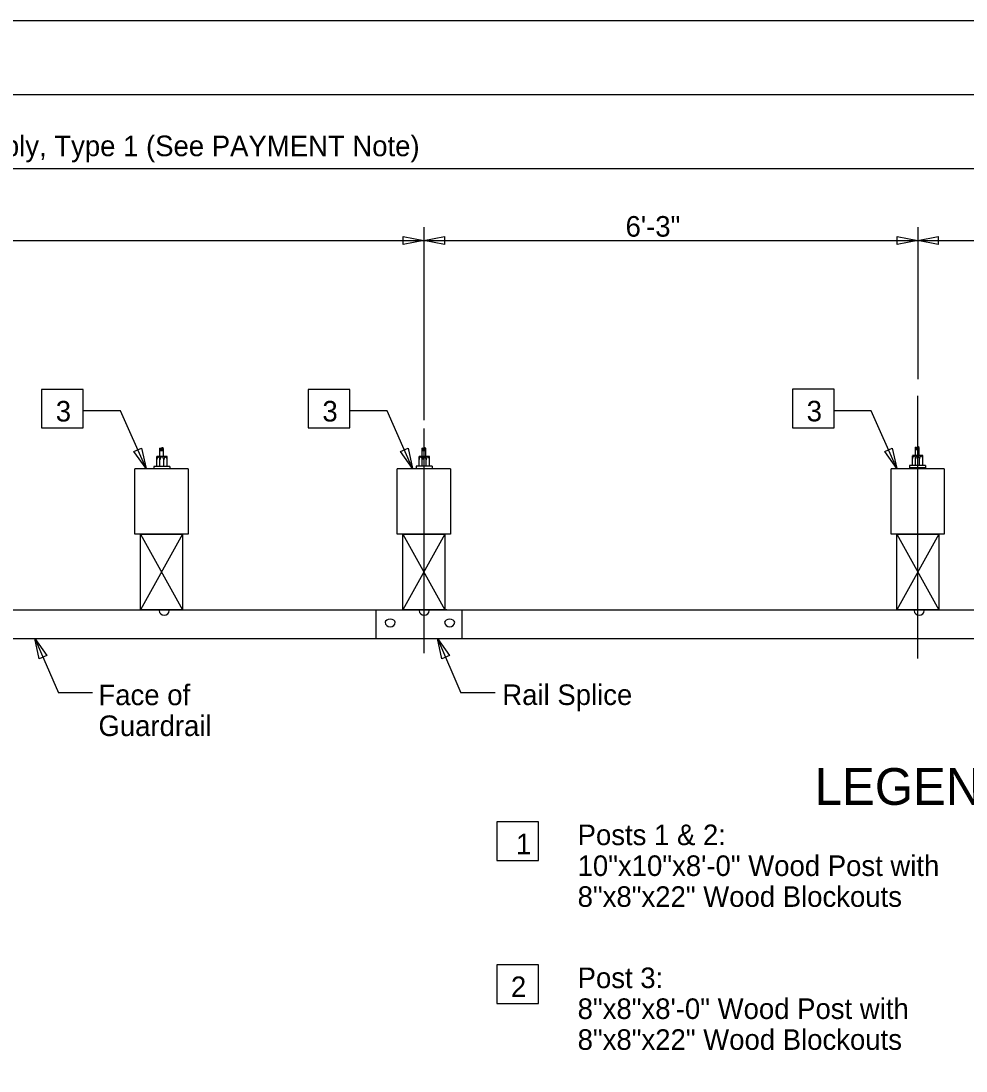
# Model space of a CAD drawing. Extents: x 0 to 34, y 0 to 22.
# Drawn here: x 12.13 to 18.56, y 14.86 to 22 of the extents above; entities that cross this region are included whole.
import ezdxf

# ---------------------------------------------------------------- set-up
doc = ezdxf.new("R2010")
doc.units = 0
for name, color, linetype in [('SH_Border', 7, 'Continuous'), ('SH_Cut_Line', 7, 'Continuous'), ('ST_Details', 7, 'Continuous'), ('ST_Text', 7, 'Continuous')]:
    doc.layers.add(name, color=color, linetype=linetype)

msp = doc.modelspace()

# ---------------------------------------------------------------- linework, layer by layer
at = {"layer": 'SH_Border'}
msp.add_lwpolyline([(2, 21.5), (33.5, 21.5), (33.5, 0.5), (2, 0.5)], close=True, dxfattribs=at)
at = {"layer": 'SH_Cut_Line'}
msp.add_lwpolyline([(0, 0), (34, 0), (34, 22), (0, 22)], close=True, dxfattribs=at)
at = {"layer": 'ST_Details'}
for p, q in [((18.2297, 19.4492), (18.2297, 17.664)), ((14.8702, 19.2267), (14.8702, 17.6984)), ((13.0734, 19.0942), (13.0811, 19.0957)), ((13.0734, 19.0434), (13.0734, 19.0942)), ((13.0991, 19.0899), (13.0734, 19.0899)), ((13.0991, 19.0832), (13.0734, 19.0832)), ((13.0991, 19.0752), (13.0734, 19.0752)), ((13.0922, 19.0957), (13.0838, 19.0957)), ((13.0991, 19.0923), (13.0922, 19.0957)), ((13.0991, 19.0415), (13.0991, 19.0923)), ((14.8591, 19.0951), (14.8668, 19.0965)), ((14.8591, 19.0442), (14.8591, 19.0951)), ((14.8847, 19.0908), (14.8591, 19.0908)), ((14.8847, 19.0841), (14.8591, 19.0841)), ((14.8847, 19.0761), (14.8591, 19.0761)), ((14.8779, 19.0965), (14.8697, 19.0965)), ((14.8847, 19.0932), (14.8779, 19.0965)), ((14.8847, 19.0423), (14.8847, 19.0932)), ((18.2171, 19.1007), (18.2247, 19.1021)), ((18.2171, 19.0497), (18.2171, 19.1007)), ((18.2425, 19.0964), (18.2171, 19.0964)), ((18.2425, 19.0896), (18.2171, 19.0896)), ((18.2425, 19.0816), (18.2171, 19.0816)), ((18.2357, 19.1021), (18.2274, 19.1021)), ((18.2425, 19.0988), (18.2357, 19.1021)), ((18.2425, 19.048), (18.2425, 19.0988)), ((13.124, 19.0369), (13.053, 19.0369)), ((13.053, 18.9713), (13.053, 19.0362)), ((13.0734, 18.9702), (13.0734, 19.0152)), ((13.0996, 18.9702), (13.0996, 19.0152)), ((13.124, 18.9694), (13.124, 19.0369)), ((14.9097, 19.0378), (14.8387, 19.0378)), ((14.8387, 18.9722), (14.8387, 19.0371)), ((14.8591, 18.971), (14.8591, 19.0162)), ((14.8852, 18.971), (14.8852, 19.0162)), ((14.9097, 18.9703), (14.9097, 19.0378)), ((18.2677, 19.0434), (18.1965, 19.0434)), ((18.1965, 18.9777), (18.1965, 19.0426)), ((18.2171, 18.9767), (18.2171, 19.0217)), ((18.2431, 18.9767), (18.2431, 19.0217)), ((18.2677, 18.9759), (18.2677, 19.0434)), ((12.9037, 18.5091), (12.9037, 18.9533)), ((13.2656, 18.9533), (12.9037, 18.9533)), ((13.142, 18.9533), (13.0311, 18.9533)), ((13.1417, 18.9702), (13.0334, 18.9702)), ((13.0334, 18.9702), (13.0334, 18.9533)), ((13.1417, 18.9702), (13.1417, 18.9533)), ((13.2656, 18.9533), (13.2656, 18.5091)), ((14.6894, 18.5091), (14.6894, 18.9533)), ((15.0512, 18.9533), (14.6894, 18.9533)), ((14.9276, 18.9543), (14.8169, 18.9543)), ((14.9271, 18.971), (14.8191, 18.971)), ((14.8191, 18.971), (14.8191, 18.9543)), ((14.9271, 18.971), (14.9271, 18.9543)), ((15.0512, 18.9533), (15.0512, 18.5091)), ((18.0511, 18.5091), (18.0511, 18.9533)), ((18.4129, 18.9533), (18.0511, 18.9533)), ((18.2855, 18.9598), (18.1747, 18.9598)), ((18.2851, 18.9767), (18.1767, 18.9767)), ((18.1767, 18.9767), (18.1767, 18.9598)), ((18.2851, 18.9767), (18.2851, 18.9598)), ((18.4129, 18.9533), (18.4129, 18.5091)), ((13.2656, 18.5091), (12.9037, 18.5091)), ((12.9418, 17.9934), (12.9418, 18.5091)), ((12.9418, 18.5091), (13.2275, 18.5091)), ((12.9418, 18.5091), (13.2275, 17.9934)), ((13.2275, 18.5091), (12.9418, 17.9934)), ((13.2275, 18.5091), (13.2275, 17.9934)), ((15.0512, 18.5091), (14.6894, 18.5091)), ((14.7275, 17.9934), (14.7275, 18.5091)), ((14.7275, 18.5091), (15.0131, 18.5091)), ((14.7275, 18.5091), (15.0131, 17.9934)), ((15.0131, 18.5091), (14.7275, 17.9934)), ((15.0131, 18.5091), (15.0131, 17.9934)), ((18.4129, 18.5091), (18.0511, 18.5091)), ((18.0892, 17.9934), (18.0892, 18.5091)), ((18.0892, 18.5091), (18.3749, 18.5091)), ((18.0892, 18.5091), (18.3749, 17.9934)), ((18.3749, 18.5091), (18.0892, 17.9934)), ((18.3749, 18.5091), (18.3749, 17.9934)), ((4.5018, 17.9934), (21.2687, 17.9934)), ((13.2275, 17.9934), (12.9418, 17.9934)), ((14.5458, 17.7999), (14.5458, 17.9934)), ((15.0131, 17.9934), (14.7275, 17.9934)), ((15.0278, 17.9934), (14.7422, 17.9934)), ((15.1314, 17.7999), (15.1314, 17.9934)), ((18.3749, 17.9934), (18.0892, 17.9934)), ((5.4066, 17.7999), (21.2687, 17.7999))]:
    msp.add_line(p, q, dxfattribs=at)
for centre, major_axis, ratio, start_param, end_param in [((13.0632, 19.0192), (0, -0.0142), 0.738563, 1.441228, 4.934001), ((13.0873, 19.0184), (0, -0.0169), 0.738563, 1.385306, 4.820506), ((13.1116, 19.0168), (0, -0.0162), 0.738563, 1.407193, 4.875853), ((14.8488, 19.0201), (0, -0.0142), 0.738563, 1.441228, 4.934001), ((14.873, 19.0193), (0, -0.0169), 0.738563, 1.385306, 4.820506), ((14.8972, 19.0177), (0, -0.0162), 0.738563, 1.407193, 4.875853), ((18.2067, 19.0257), (0, -0.0142), 0.738563, 1.441228, 4.934001), ((18.2309, 19.0248), (0, -0.0169), 0.738563, 1.385306, 4.820506), ((18.2551, 19.0233), (0, -0.0162), 0.738563, 1.407193, 4.875853), ((13.1035, 17.9892), (0.0342, 0), 0.943283, 3.141593, 6.283185), ((14.6414, 17.9099), (-0.0342, 0), 0.599655, 3.141593, 6.283185), ((14.873, 17.9892), (0.0342, 0), 0.943283, 3.141593, 6.283185), ((15.046, 17.9099), (-0.0342, 0), 0.599655, 3.141593, 6.283185), ((18.2425, 17.9892), (0.0342, 0), 0.943283, 3.141593, 6.283185), ((14.6414, 17.9099), (0.0342, 0), 0.943283, 3.141593, 6.283185), ((15.046, 17.9099), (0.0342, 0), 0.943283, 3.141593, 6.283185)]:
    msp.add_ellipse(centre, major_axis=major_axis, ratio=ratio, start_param=start_param, end_param=end_param, dxfattribs=at)
at = {"layer": 'ST_Text'}
for p, q in [((4.1607, 20.997), (21.5938, 20.997)), ((14.8702, 20.5977), (14.8702, 19.2852)), ((18.2321, 20.5977), (18.2321, 19.5626)), ((7.7279, 20.5064), (14.8702, 20.5064)), ((14.8702, 20.5064), (18.2321, 20.5064)), ((18.2321, 20.5064), (23.3868, 20.5064)), ((12.268, 19.4936), (12.268, 19.2317)), ((12.5519, 19.4936), (12.268, 19.4936)), ((12.5519, 19.2317), (12.5519, 19.4936)), ((14.0828, 19.4936), (14.0828, 19.2317)), ((14.3667, 19.4936), (14.0828, 19.4936)), ((14.3667, 19.2317), (14.3667, 19.4936)), ((17.3792, 19.4943), (17.3792, 19.2325)), ((17.6631, 19.4943), (17.3792, 19.4943)), ((17.6631, 19.2325), (17.6631, 19.4943)), ((12.268, 19.2317), (12.5519, 19.2317)), ((14.0828, 19.2317), (14.3667, 19.2317)), ((17.3792, 19.2325), (17.6631, 19.2325)), ((12.2227, 17.7999), (12.3825, 17.4295)), ((14.9631, 17.7999), (15.1231, 17.4295)), ((12.6153, 17.4295), (12.3825, 17.4295)), ((15.3558, 17.4295), (15.1231, 17.4295)), ((15.3661, 16.5509), (15.3661, 16.2892)), ((15.65, 16.5509), (15.3661, 16.5509)), ((15.65, 16.2892), (15.65, 16.5509)), ((15.3661, 16.2892), (15.65, 16.2892)), ((15.3661, 15.5783), (15.3661, 15.3165)), ((15.65, 15.5783), (15.3661, 15.5783)), ((15.65, 15.3165), (15.65, 15.5783)), ((15.3661, 15.3165), (15.65, 15.3165))]:
    msp.add_line(p, q, dxfattribs=at)
for points in [[(14.7302, 20.4784), (14.7302, 20.5344), (14.8702, 20.5064)], [(15.0102, 20.5344), (15.0102, 20.4784), (14.8702, 20.5064)], [(18.0921, 20.4784), (18.0921, 20.5344), (18.2321, 20.5064)], [(18.3721, 20.5344), (18.3721, 20.4784), (18.2321, 20.5064)], [(12.8968, 19.0712), (12.948, 19.094), (12.9792, 18.9547)], [(14.7116, 19.0713), (14.7628, 19.094), (14.794, 18.9547)], [(18.0078, 19.072), (18.059, 19.0947), (18.0902, 18.9554)], [(12.3038, 17.6825), (12.2524, 17.6603), (12.2227, 17.7999)], [(15.0443, 17.6825), (14.9929, 17.6603), (14.9631, 17.7999)]]:
    msp.add_lwpolyline(points, close=True, dxfattribs=at)
for points in [[(12.9792, 18.9547), (12.8046, 19.3476), (12.5524, 19.3476)], [(14.794, 18.9547), (14.6195, 19.3476), (14.3672, 19.3476)], [(18.0902, 18.9554), (17.9157, 19.3484), (17.6635, 19.3484)]]:
    msp.add_lwpolyline(points, dxfattribs=at)

# ---------------------------------------------------------------- texts
for s, height, p in [('Item 606 Guardrail Type 5 and Item 606 Bridge Terminal Assembly, Type 1 (See PAYMENT Note)', 0.14, (6.6944, 21.0803)), ('6\'-3"', 0.14, (16.2434, 20.5329)), ('3', 0.14, (12.3649, 19.2754)), ('3', 0.14, (14.1797, 19.2754)), ('3', 0.14, (17.4761, 19.2762)), ('Face of', 0.14, (12.6554, 17.3456)), ('Rail Splice', 0.14, (15.4046, 17.3466)), ('Guardrail', 0.14, (12.6554, 17.1356)), ('LEGEND', 0.25, (17.5314, 16.6675)), ('Posts 1 & 2:', 0.14, (15.917, 16.3935)), ('1', 0.14, (15.498, 16.3317)), ('10"x10"x8\'-0" Wood Post with', 0.14, (15.917, 16.1835)), ('8"x8"x22" Wood Blockouts', 0.14, (15.917, 15.9735)), ('2', 0.14, (15.463, 15.3599)), ('Post 3:', 0.14, (15.917, 15.4207)), ('8"x8"x8\'-0" Wood Post with', 0.14, (15.917, 15.2107)), ('8"x8"x22" Wood Blockouts', 0.14, (15.917, 15.0007))]:
    msp.add_text(s, height=height, dxfattribs=at).set_placement(p)

doc.saveas('drawing.dxf')
